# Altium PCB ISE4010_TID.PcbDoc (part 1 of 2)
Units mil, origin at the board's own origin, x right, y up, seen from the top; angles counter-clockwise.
Board outline 9000 x 8000 mil, 4 copper layers (Layer 1 - Top Layer, Layer 2 - GND, Layer 3 - PWR, Layer 4 - Bottom Layer), stack 65.6 mil thick; 159 components, 101 nets, 426 pads, 332 vias.
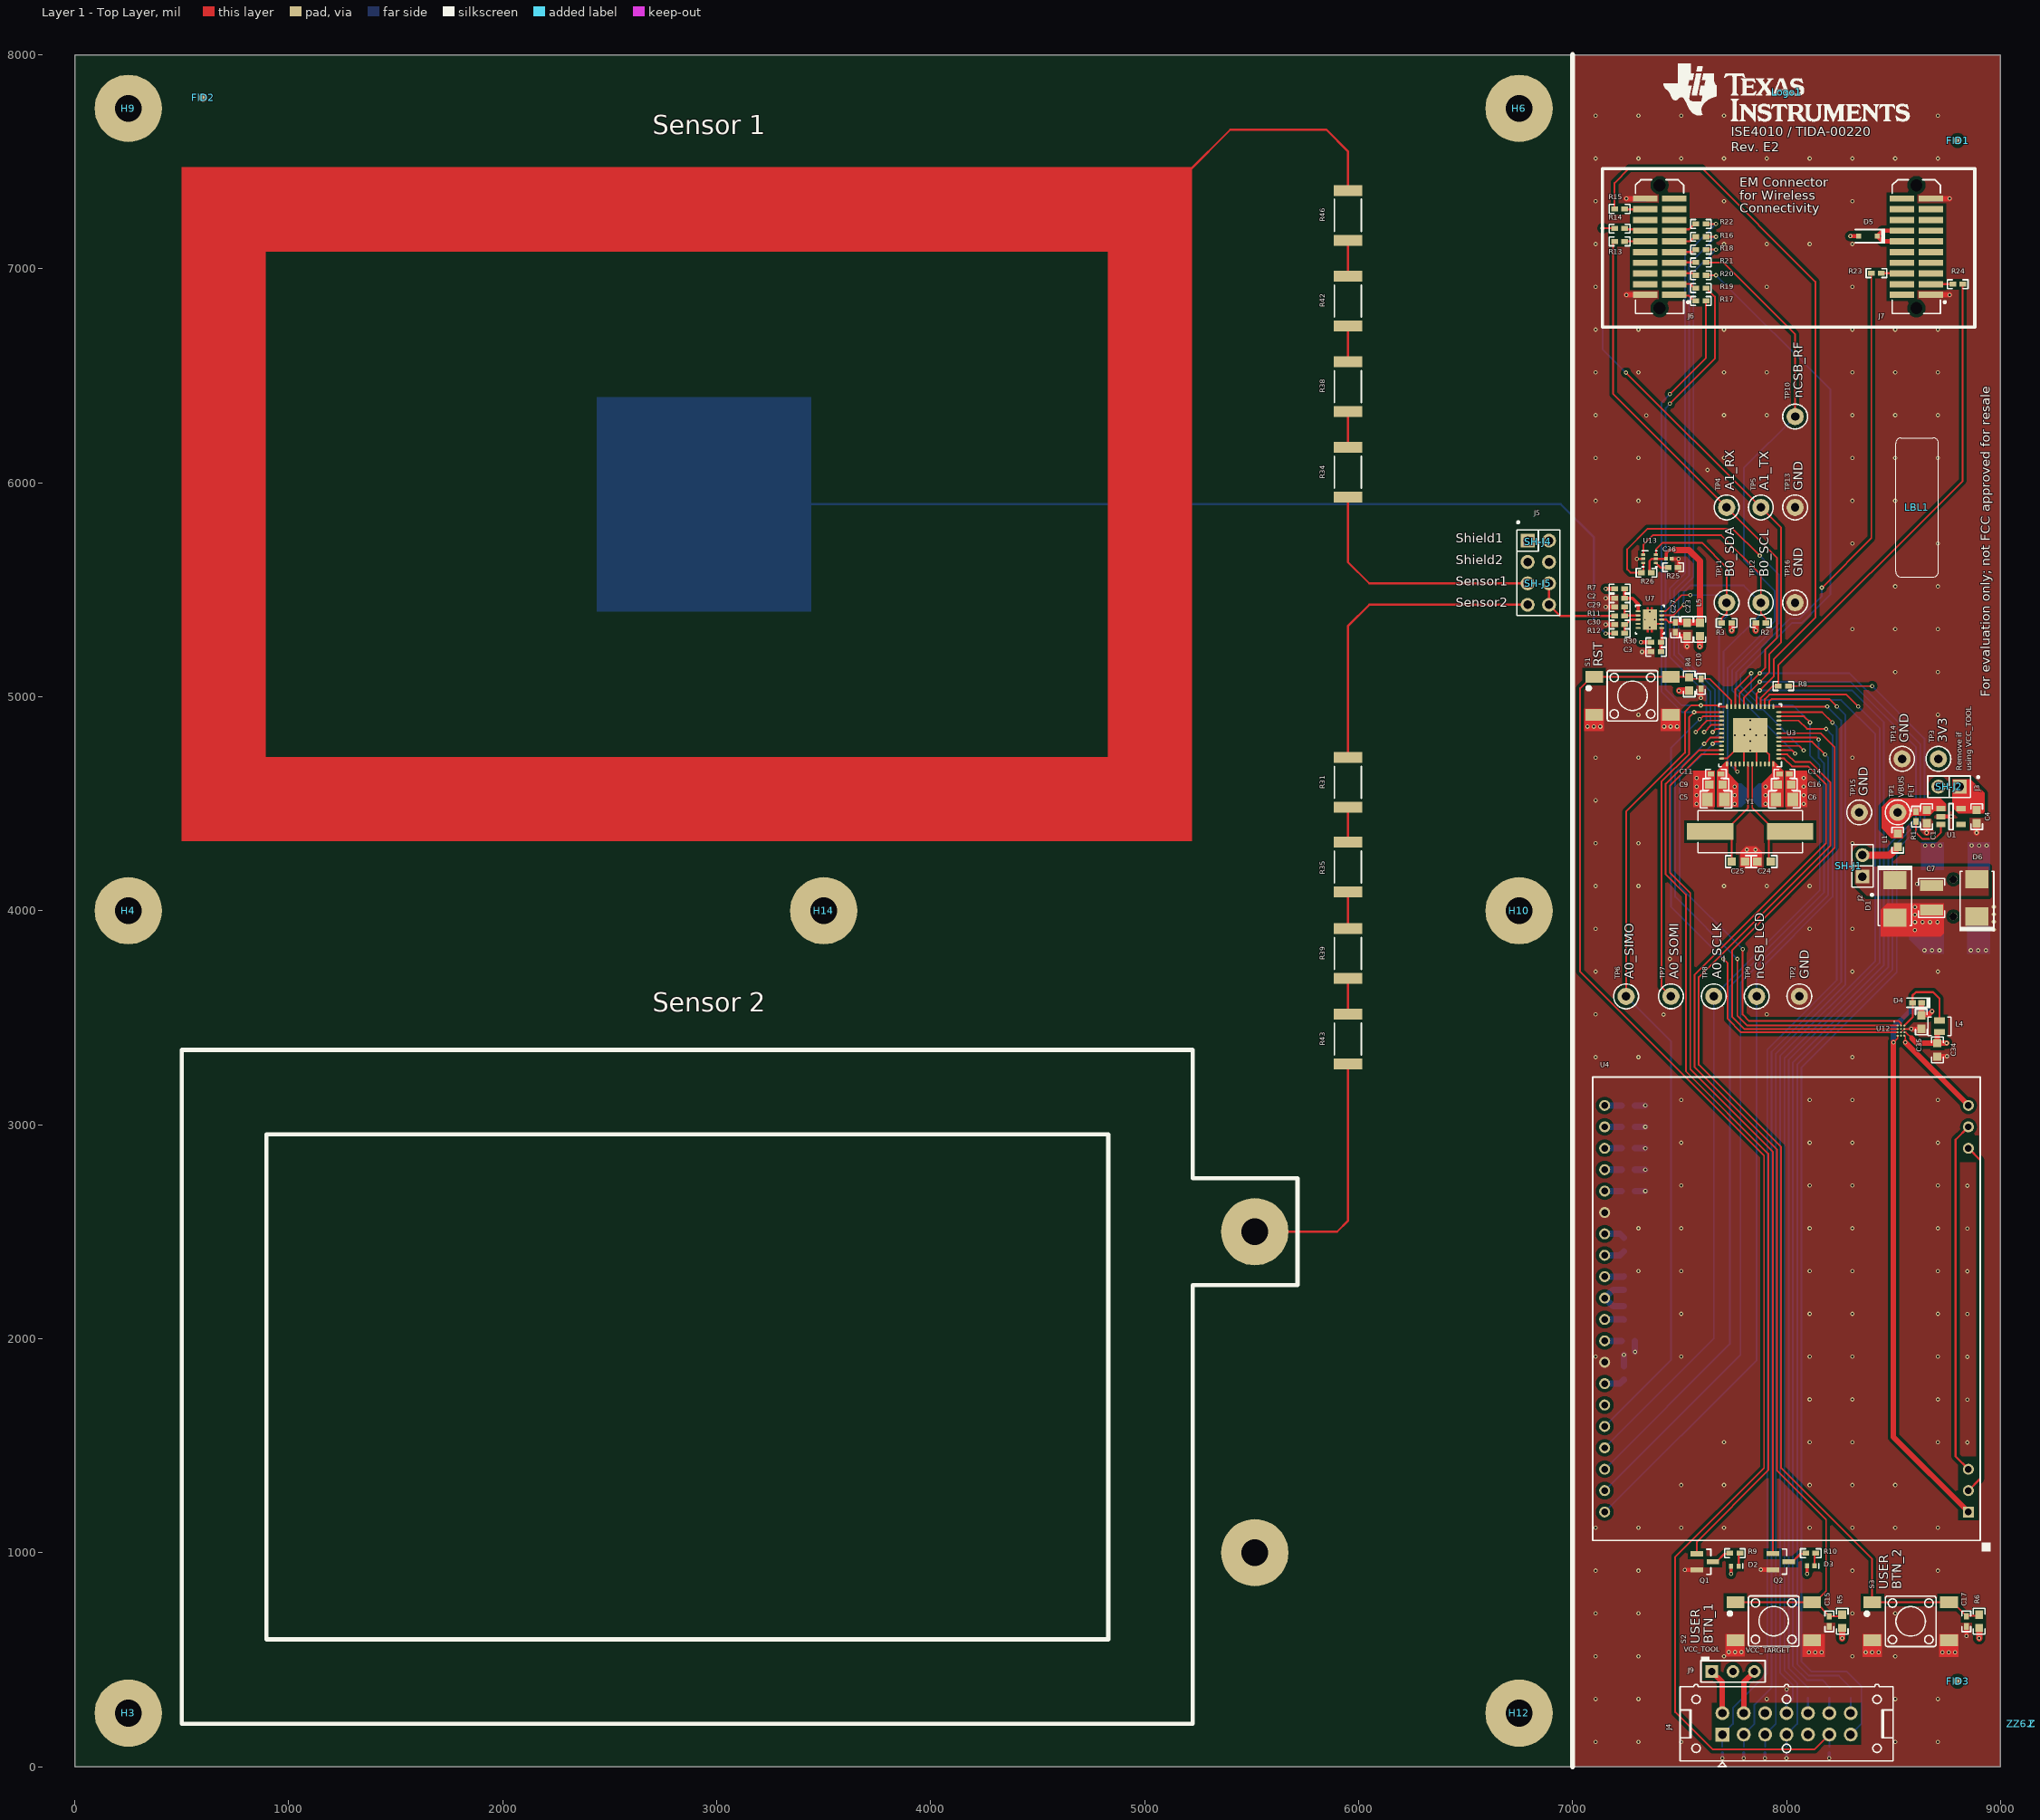
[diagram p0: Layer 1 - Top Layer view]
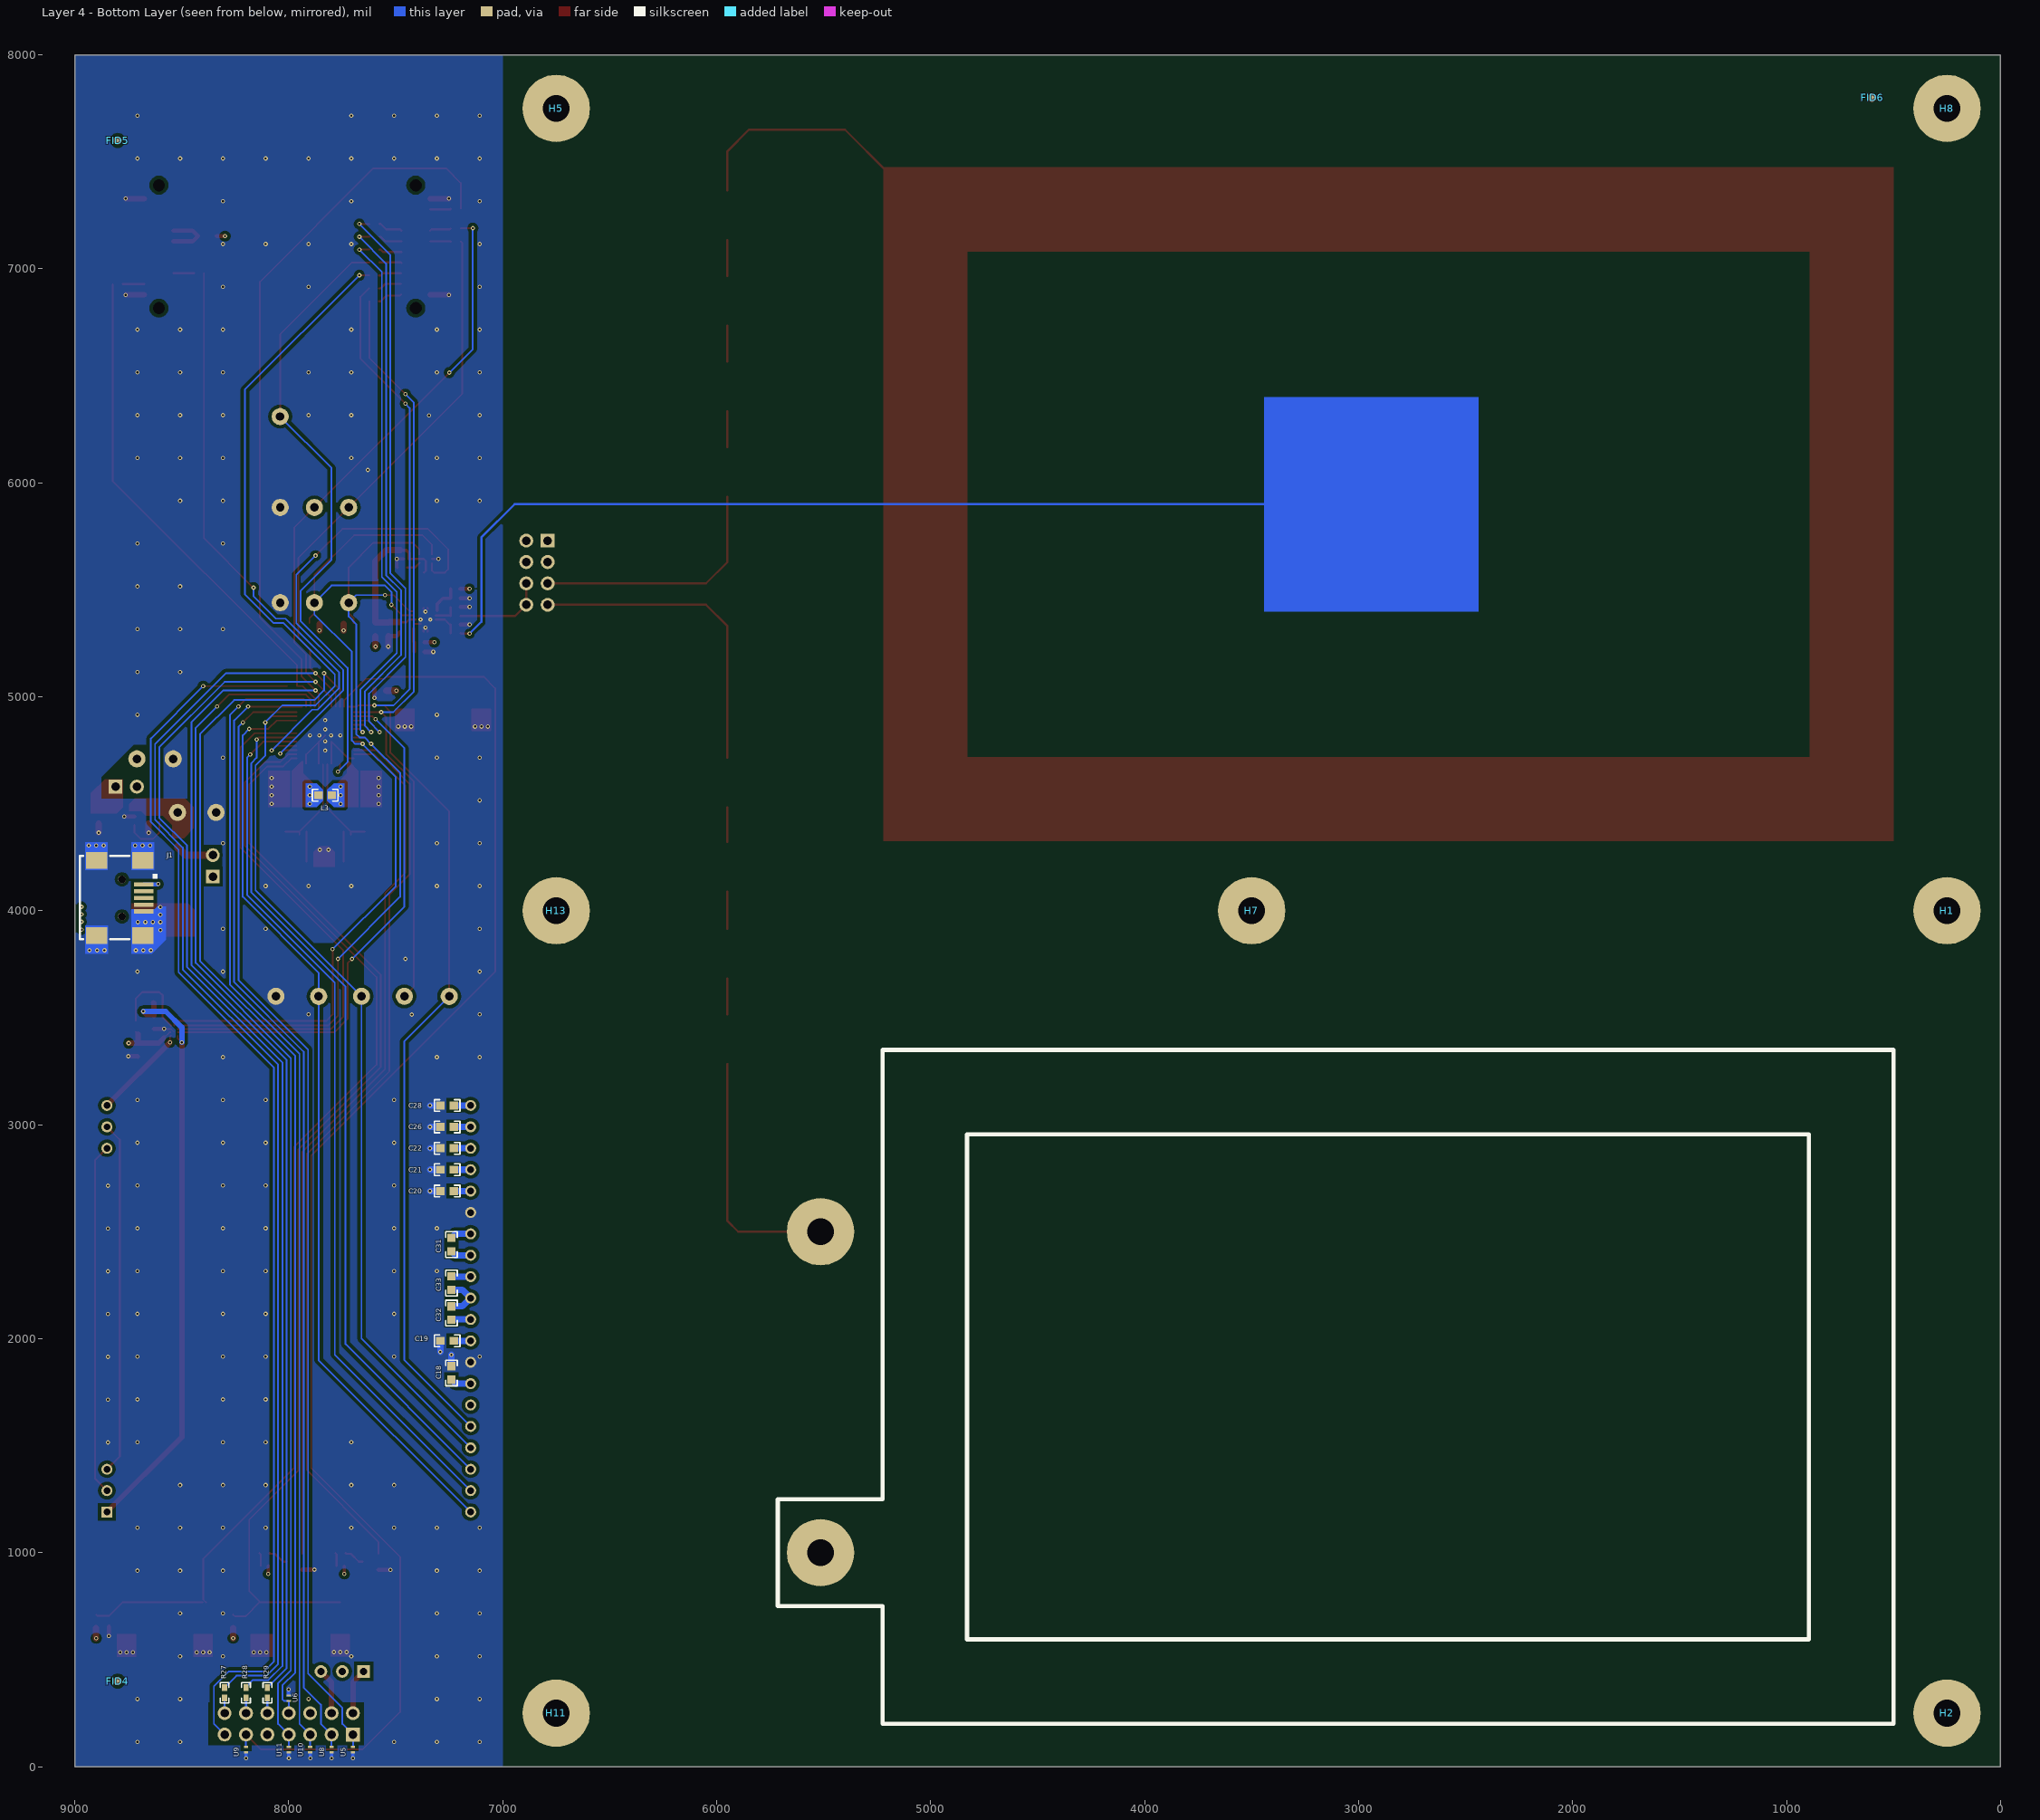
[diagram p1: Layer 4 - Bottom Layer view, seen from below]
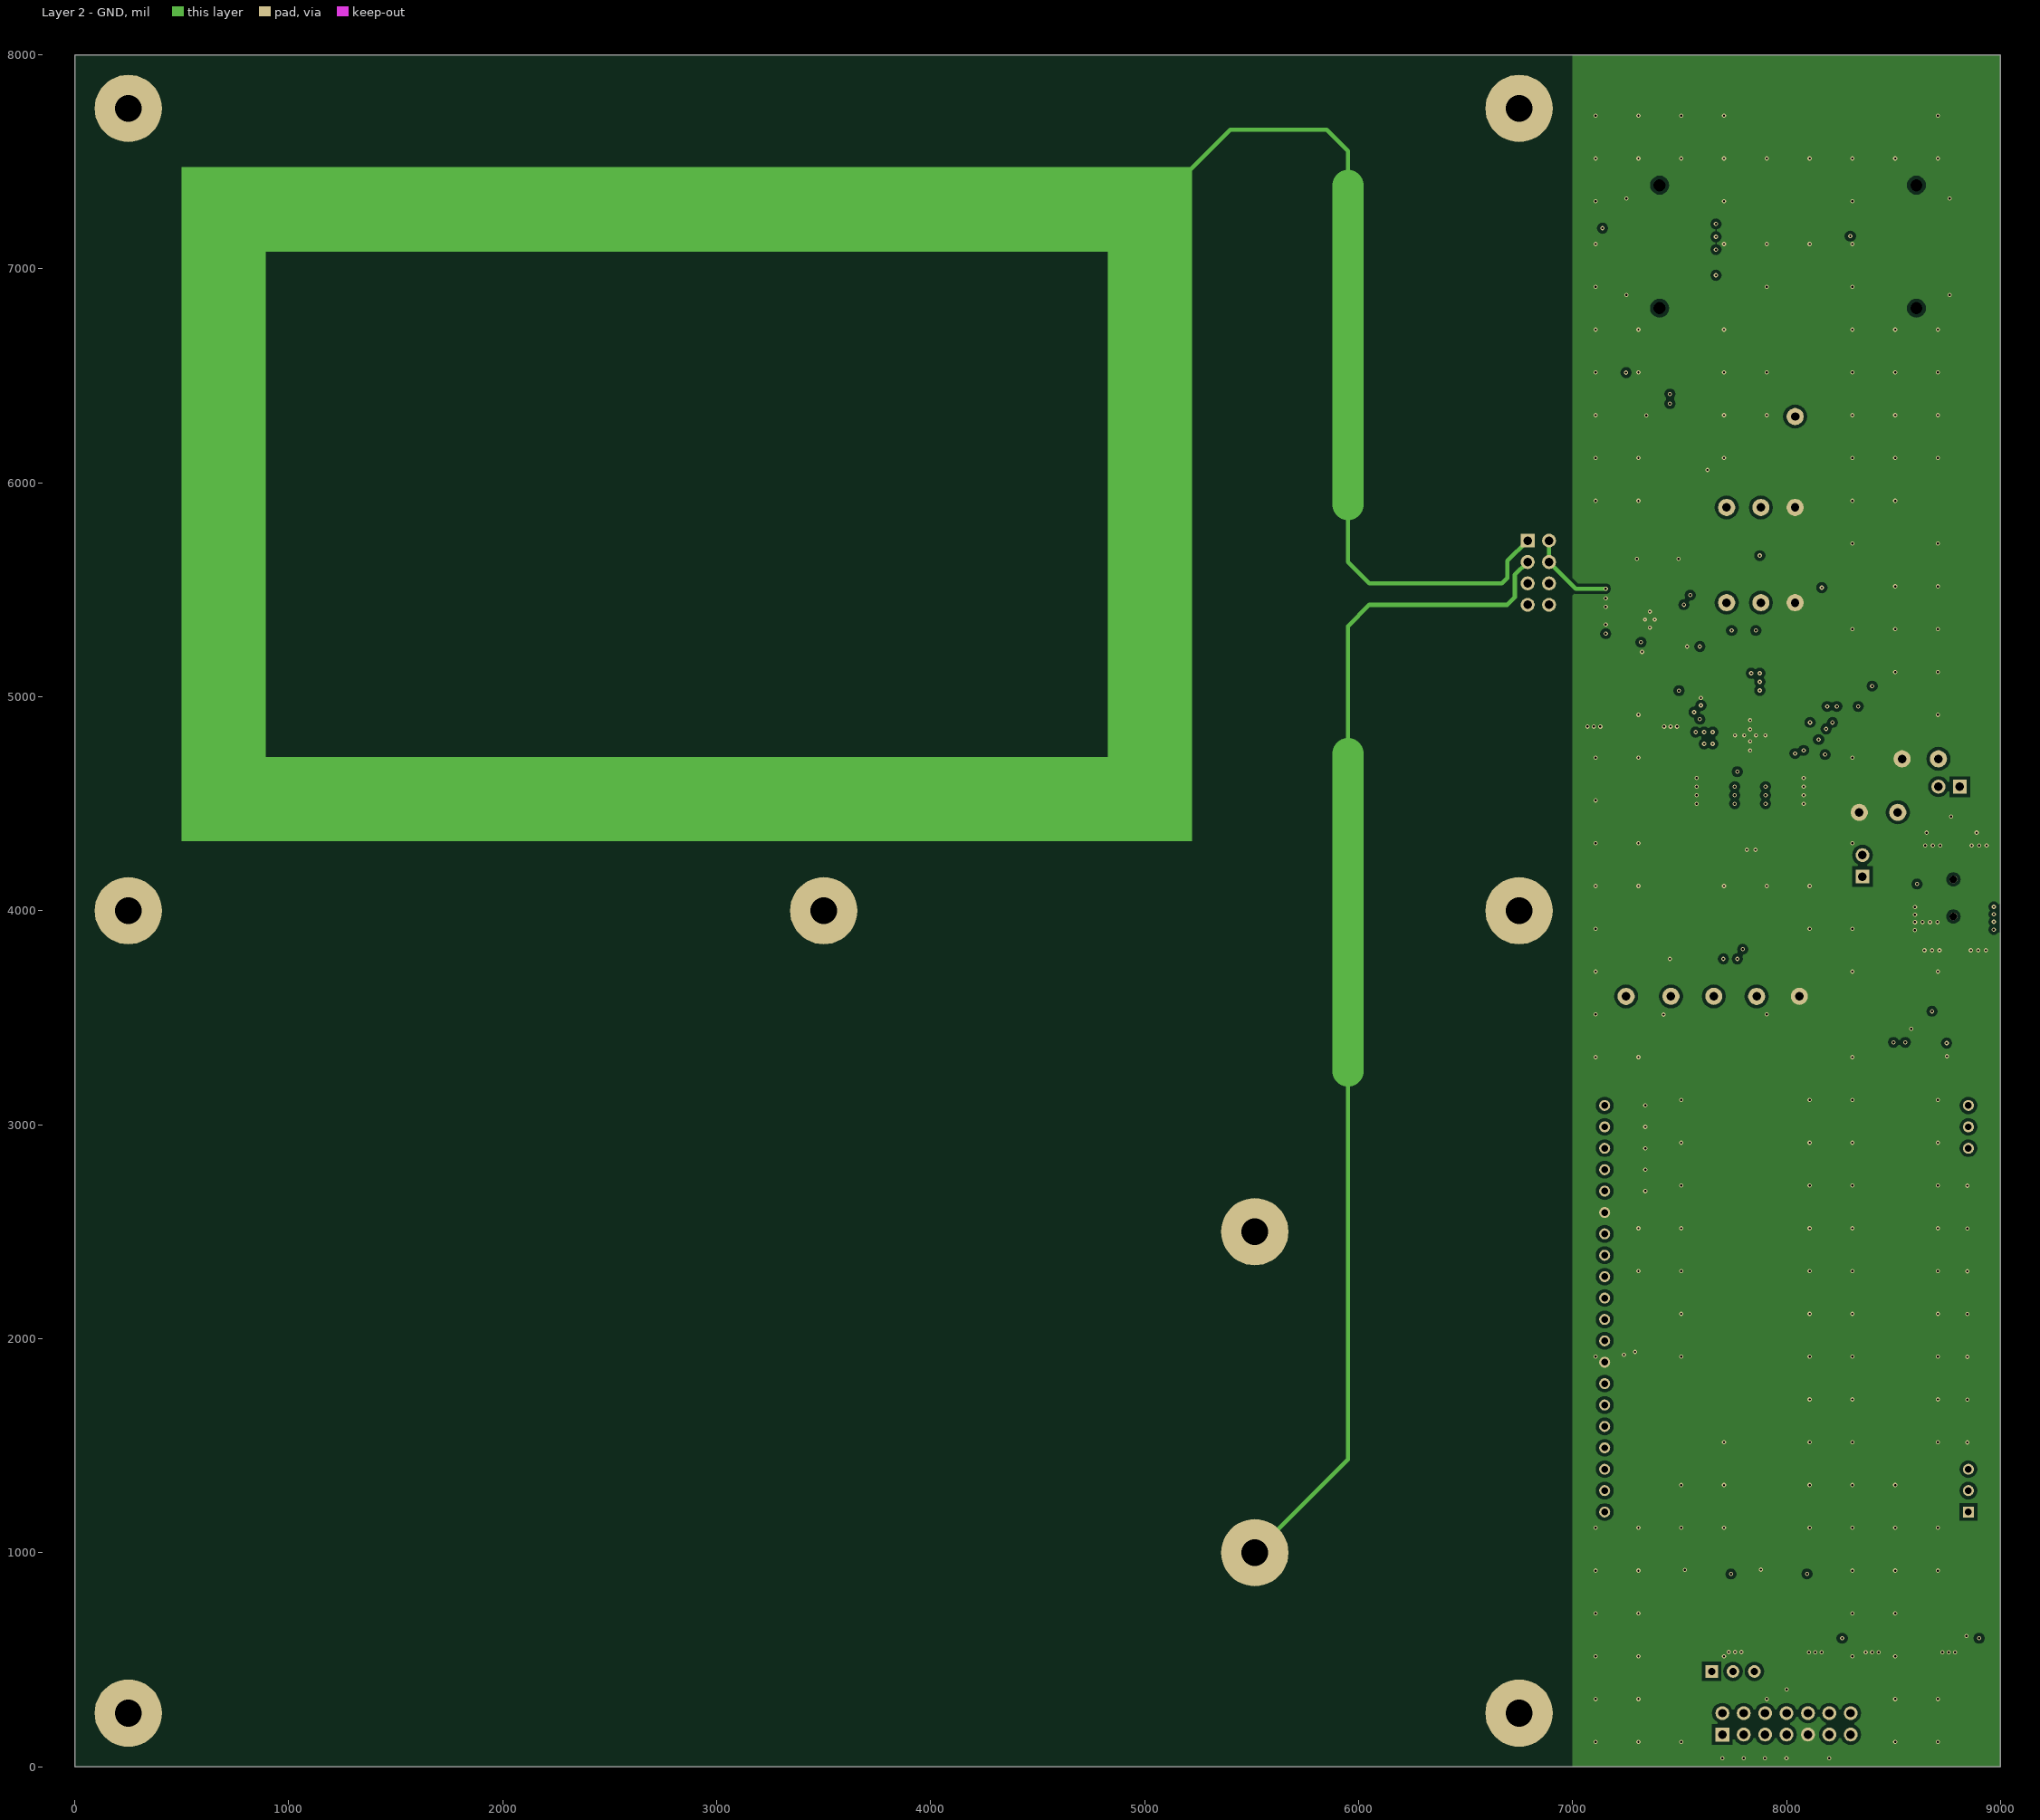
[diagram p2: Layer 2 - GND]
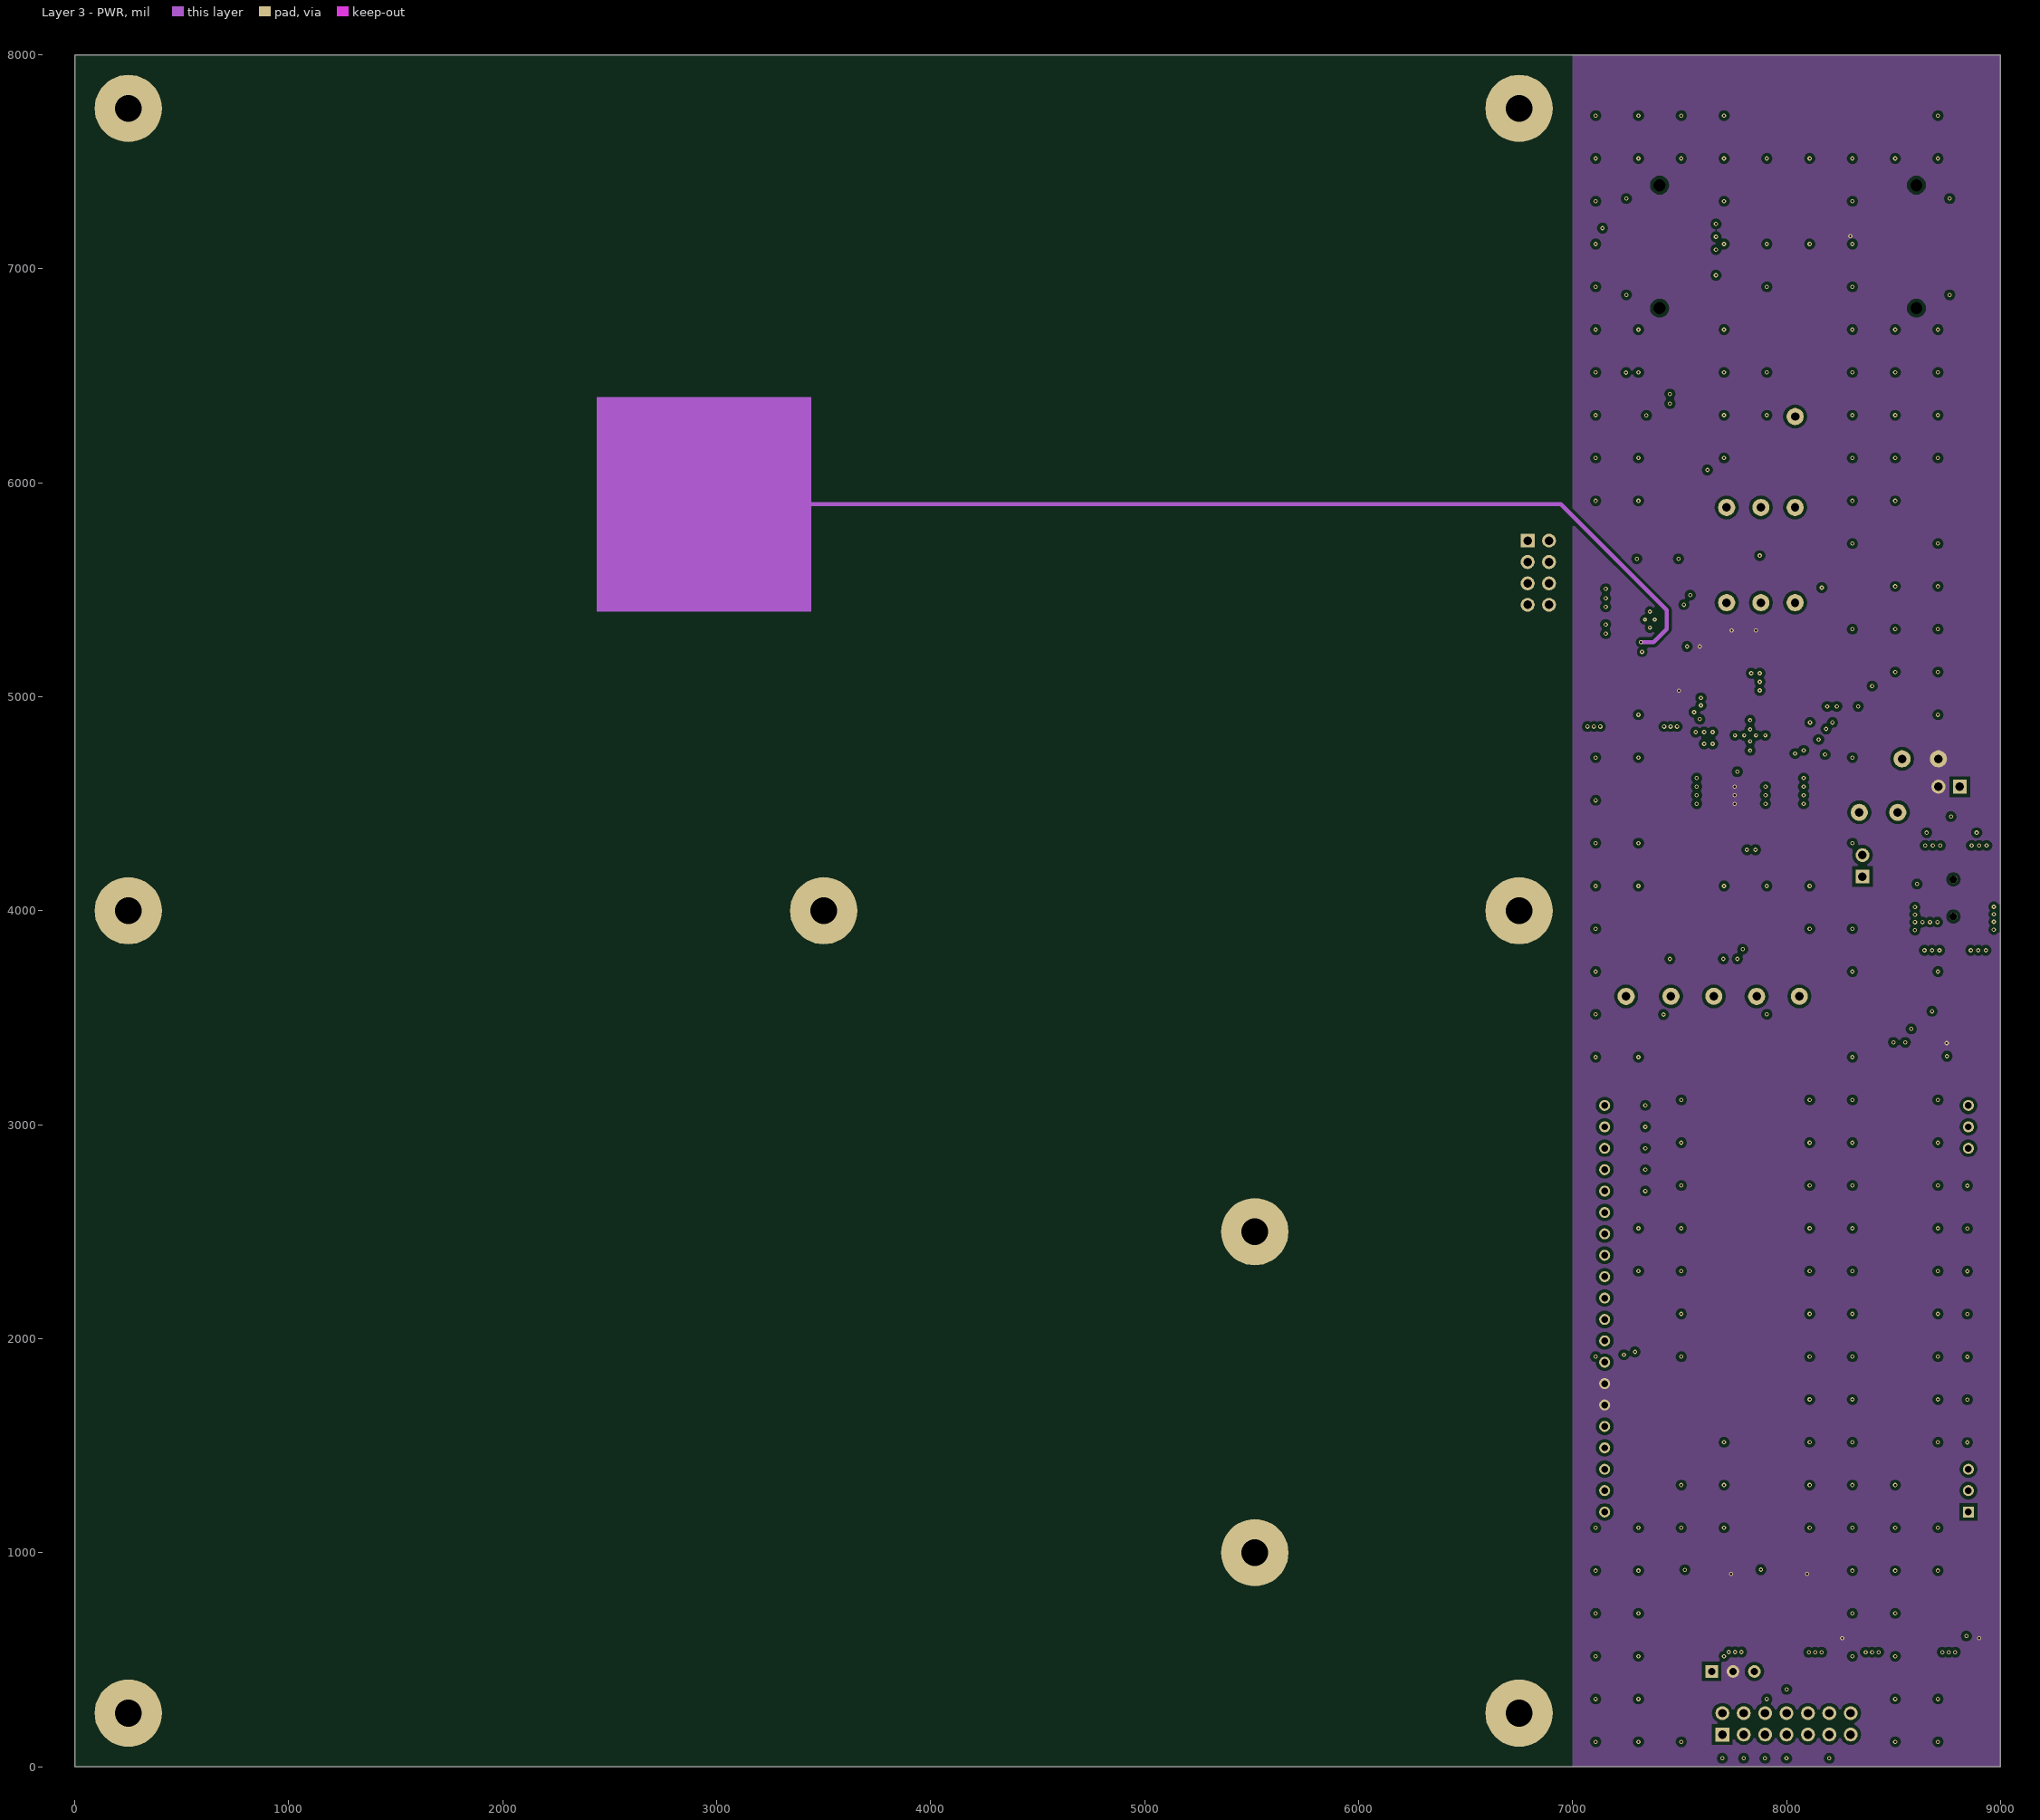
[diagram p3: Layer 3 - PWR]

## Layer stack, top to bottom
Layer 1 - Top Layer: signal copper 1.4
Dielectric: core 10, 370HR, Dk 4.8
Layer 2 - GND: signal copper 1.4
Dielectric: prepreg 40, 370HR, Dk 4.8
Layer 3 - PWR: signal copper 1.4
Dielectric: core 10, 370HR, Dk 4.8
Layer 4 - Bottom Layer: signal copper 1.4

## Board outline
0,0 0,8000 9000,8000 9000,0

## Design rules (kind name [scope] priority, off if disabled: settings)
AcuteAngle [All] p1: minimum=4.50000000000000E+0001 checktracksonly=FALSE
AssemblyTestPointUsage [All] p1: valid=2
Clearance "Stitching GND" [IsStitchingVia and InNet('GND') vs (IsVia and (Not IsStitchingVia)) Or IsPad] p1: gap=8
Clearance Clearance_U12 [InComponent('U12')] p2: gap=3.4
Clearance Clearance_BoardEdge_MountingHoles [OnCopper and InComponentClass('Mounting Holes') vs IsKeepOut] p3: gap=20
Clearance Clearance_BoardEdge_Poly [OnCopper and InPoly vs IsKeepOut] p4: gap=20
Clearance Clearance_BoardEdge [OnCopper and Not InComponentClass('Logo') and not InComponentClass('FiducialMark') and not InRegion(1000,500,4000,800) vs IsKeepOut] p5: gap=20
Clearance Clearance_Poly [InPolygon] p6: gap=15
Clearance [All] p7: gap=5.5
ComponentClearance ComponentClearance_Shunt [InComponentClass('Header') vs InComponentClass('Shunt')] p1 off: gap=0 collisioncheckmode=3 verticalgap=0 showdistances=FALSE
ComponentClearance ComponentClearance_MountingHoles_FiducialMarks [InComponentClass('Mounting Holes') vs InComponentClass('FiducialMark')] p2 off: gap=50 collisioncheckmode=3 verticalgap=10 showdistances=FALSE
ComponentClearance ComponentClearance_Logo [InComponentClass(Logo)] p3 off: gap=50 collisioncheckmode=3 verticalgap=10 showdistances=FALSE
ComponentClearance ComponentClearance_ScrewToNut [(HasFootprint('NY PMS 440 0025 PH')) vs (HasFootprint('Keystone_1902C'))] p4 off: gap=5 collisioncheckmode=3 verticalgap=10 showdistances=FALSE
ComponentClearance ComponentClearance_MountingHoles [InComponentClass('Mounting Holes')] p5 off: gap=250 collisioncheckmode=3 verticalgap=100000 showdistances=FALSE
ComponentClearance ComponentClearance_SmallPassives [HasFootprint('0201*') or HasFootprint('0402*') or HasFootprint('0508') or HasFootprint('0603*') or HasFootprint('0612') or HasFootprint('0805*') or HasFootprint('0815*') or HasFootprint('0830*') or HasFootprint('1206*') or HasFootprint('1210*') or HasFootprint('1808*') or HasFootprint('1812*') or HasFootprint('1825*') or HasFootprint('2010*') or HasFootprint('2220*') or HasFootprint('2225*') or HasFootprint('2512*') or HasFootprint('2728*') or HasFootprint('3518*') vs HasFootprint('0201*') or HasFootprint('0402*') or HasFootprint('0508') or HasFootprint('0603*') or HasFootprint('0612') or HasFootprint('0805*') or HasFootprint('0815*') or HasFootprint('0830*') or HasFootprint('1206*') or HasFootprint('1210*') or HasFootprint('1808*') or HasFootprint('1812*') or HasFootprint('1825*') or HasFootprint('2010*') or HasFootprint('2220*') or HasFootprint('2225*') or HasFootprint('2512*') or HasFootprint('2728*') or HasFootprint('3518*')] p6 off: gap=20 collisioncheckmode=3 verticalgap=10 showdistances=FALSE
ComponentClearance ComponentClearance_THtoSMT [IsThruComponent vs IsSMTComponent] p7 off: gap=100 collisioncheckmode=3 verticalgap=100000 showdistances=FALSE
ComponentClearance ComponentClearance_THtoTH [IsThruComponent vs IsThruComponent] p8 off: gap=118.11 collisioncheckmode=3 verticalgap=100000 showdistances=FALSE
ComponentClearance [All] p9 off: gap=5 collisioncheckmode=3 verticalgap=10 showdistances=FALSE
DiffPairsRouting [All] p1: maxlimit=100 minlimit=10 mostfreqgap=10 maxuncoupledlength=1000
FabricationTestPointUsage TestPointUsage [All] p1: valid=2 allowmultiple=FALSE
FabricationTestpoint Testpoint [All] p1: side=3 testpointundercomponent=TRUE minsize=40 maxsize=100 preferedsize=60 minholesize=0 maxholesize=40 preferedholesize=32 testpointgrid=1 allowsidetop=TRUE allowsidebottom=TRUE usegrid=TRUE gridtolerance=0.01
FanoutControl Fanout_LCC [IsLCC] p1: bgadir=Out bgaviamode=Centered fanoutstyle=Auto fanoutdirection=Alternating viagrid=1 // Fanout_LCC (Default Rule)
FanoutControl Fanout_BGA [IsBGA] p2: bgadir=Out bgaviamode=Centered fanoutstyle=Auto fanoutdirection=Alternating viagrid=1 // Fanout_BGA (Default Rule)
FanoutControl Fanout_Default [All] p4: bgadir=Out bgaviamode=Centered fanoutstyle=Auto fanoutdirection=Alternating viagrid=1 // Fanout_Default (Default Rule)
FanoutControl Fanout_Small [(CompPinCount < 5)] p5: bgadir=Out bgaviamode=Centered fanoutstyle=Auto fanoutdirection=OutThenIn viagrid=1 // Fanout_Small (Default Rule)
HoleSize [All] p1: absolutevalues=TRUE maxlimit=550 minlimit=5 maxpercent=80.000 minpercent=20.000
MinimumAnnularRing MinimumAnnularRing_ThermalPadVias [IsVia and InAnyComponent] p1: minimumring=5.91
MinimumAnnularRing [All] p2: minimumring=5
MinimumSolderMaskSliver MinimumSolderMaskSliver_Logo [InComponentClass('Logo') vs InComponentClass('Logo')] p1: minsoldermaskwidth=0.7
MinimumSolderMaskSliver [All] p2: minsoldermaskwidth=4
NetAntennae [All] p1 off: netantennaetolerance=0
PlaneClearance [All] p1: clearance=10
PlaneConnect [All] p1: planeconnectstyle=Relief reliefexpansion=10 reliefentries=4 reliefconductorwidth=10 reliefairgap=10
PolygonConnect [All] p1: connectstyle=Direct reliefconductorwidth=10 reliefentries=4 polygonreliefangle="90 Angle" airgapwidth=10
RoutingVias ThermalPadVias [IsVia and InAnyComponent] p1: holewidth=7.87 width=19.68 viastyle="Through Hole" minholewidth=7.87 minwidth=19.68 maxholewidth=12.99 maxwidth=23.62
RoutingVias [All] p2: holewidth=12 width=28 viastyle="Through Hole" minholewidth=5 minwidth=20 maxholewidth=100 maxwidth=150
SMDToCorner [All] p1: distance=30000
SilkToSilkClearance [All] p1: silktosilkclearance=5
SilkscreenOverComponentPads [IsPad] p1: minsilkscreentomaskgap=4
SolderMaskExpansion [All] p1: expansion=3
Width "Schematic Width Constraint_4" [InNet('VBUS_FLT')] p1: maxlimit=100 minlimit=5 preferedwidth=25
Width "Schematic Width Constraint_3" [InNet('NetC7_1')] p2: maxlimit=100 minlimit=5 preferedwidth=25
Width "Schematic Width Constraint_2" [InNet('NetC4_2')] p3: maxlimit=100 minlimit=5 preferedwidth=25
Width "Schematic Width Constraint" [InNet('3V3')] p4: maxlimit=100 minlimit=5 preferedwidth=25
Width [All] p5: maxlimit=394 minlimit=4 preferedwidth=10 checkconnectedcopper=TRUE
12 further rules are at their usual default settings.

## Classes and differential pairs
component class Header: J3 J5
component class AssemblyNote: ZZ1 ZZ2 ZZ3 ZZ4 ZZ5 ZZ6 ZZ6.A ZZ6.B ZZ6.C ZZ6.D
component class FiducialMark: FID1 FID2 FID3 FID4 FID5 FID6
component class ISE4010_TID_Hardware: FID1 FID2 FID3 FID4 FID5 FID6 H1 H2 H3 H4 H5 H6 H7 H8 H9 H10 H11 H12 H13 H14 LBL1 Logo1 ZZ1 ZZ2 ZZ3 ZZ4 ZZ5 ZZ6 ZZ6.A ZZ6.B ZZ6.C ZZ6.D
component class Logo: Logo1
component class ISE4010_MSP430: C1 C4 C5 C6 C7 C9 C10 C11 C14 C15 C16 C17 C24 C25 D1 D2 D3 D5 D6 J1 J2 J3 J4 J6 J7 J9 L1 L3 Q1 Q2 R1 R2 R3 R4 R5 R6 R8 R9 R10 R13 R14 R15 R16 R17 R18 R19 R20 R21 R22 R23 R24 R27 R28 R29 S1 S2 S3 SH-J1 SH-J2 TP1 TP2 TP3 TP4 TP5 TP6 TP7 TP8 TP9 TP10 TP11 TP12 TP13 TP14 TP15 TP16 U1 U3 U5 U6 U8 U9 U10 U11 Y1
component class ISE4010_FDC_LCD: C2 C3 C18 C19 C20 C21 C22 C23 C26 C27 C28 C29 C30 C31 C32 C33 C34 C35 C36 D4 J5 L4 L5 R7 R11 R12 R25 R26 R30 R31 R34 R35 R38 R39 R42 R43 R46 SH-J4 SH-J5 U4 U7 U12 U13
component class Shunt: SH-J1 SH-J2 SH-J4 SH-J5
component class "Mounting Holes": H3 H4 H6 H9 H10 H12 H14
component class Label: LBL1

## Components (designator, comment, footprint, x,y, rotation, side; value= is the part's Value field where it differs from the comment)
C1 "GRM188R71A225KE15D" 0603 8655,4440 r90 top
C2 "Used in BOM report" 0402 7220,5460 r180 top
C3 "Used in BOM report" 0402 7390,5210 r180 top
C4 "GRM188R71A225KE15D" 0603 8888.54,4440 r90 top
C5 "C2012X7R0J106M125AB" 0805_HV 7670,4520 r180 top
C6 "C2012X7R0J106M125AB" 0805_HV 7990,4520 r0 top
C7 "C1210C102KGRACTU" 1210 8677.64,4060 r270 top
C9 "C1608X7R1C105K" 0603 7670,4590 r0 top
C10 "C1005X7R1H222K" 0402 7600,5060 r270 top
C11 "GRM155R71C104KA88D" 0402 7670,4640 r0 top
C14 "GRM155R71C104KA88D" 0402 7990,4640 r180 top
C15 "C1005X7R1H222K" 0402 8200.25,679.12 r270 top
C16 "C1608X7R1C105K" 0603 7990,4590 r180 top
C17 "C1005X7R1H222K" 0402 8840.25,679.12 r270 top
C18 "C1608X7R1C105K" 0603 7240,1840 r90 bottom
C19 "C1608X7R1C105K" 0603 7260,1990 r0 bottom
C20 "C1608X7R1C105K" 0603 7260,2690 r0 bottom
C21 "C1608X7R1C105K" 0603 7260,2790 r0 bottom
C22 "C1608X7R1C105K" 0603 7260,2890 r0 bottom
C23 "C1608X7R1C105K" 0603 7535,5315 r270 top
C24 "GRM1885C2A180JA01D" 0603 7895,4230 r180 top
C25 "GRM1885C2A180JA01D" 0603 7775,4230 r0 top
C26 "C1608X7R1C105K" 0603 7260,2990 r0 bottom
C27 "GRM155R71C104KA88D" 0402 7480,5325 r90 top
C28 "C1608X7R1C105K" 0603 7260,3090 r0 bottom
C29 "GRM1555C1H820JA01D" 0402 7220,5420 r0 top
C30 "GRM1555C1H820JA01D" 0402 7220,5337.99 r0 top
C31 "C1608X7R1C105K" 0603 7240,2440 r90 bottom
C32 "C1608X7R1C105K" 0603 7240,2120 r90 bottom
C33 "C1608X7R1C105K" 0603 7240,2260 r90 bottom
C34 "GRM188R71A225KE15D" 0603 8704.92,3349.92 r270 top
C35 "UMK107AB7105KA-T" 0603 8629.92,3479.92 r270 top
C36 "GRM033R71A103KA01D" 0201 7450,5645 r0 top
D1 "1SMB5919BT3G" SMB 8506.54,4055.39 r270 top
D2 "SML-P12PTT86" SML-P1_GREEN 7758.43,937.4 r180 top
D3 "SML-P12PTT86" SML-P1_GREEN 8113.43,937.86 r180 top
D4 "NSR0240V2T1G" SOD-523 8609.92,3569.92 r180 top
D5 "1SS315TPH3F" sod-323 8381,7153 r180 top
D6 "SMBJ6.0CA" SMB 8890,4060 r90 top
FID1 "Fiducial" Fiducial10-20 8800,7600 r0 top
FID2 "Fiducial" Fiducial10-20 600,7800 r0 top
FID3 "Fiducial" Fiducial10-20 8800,400 r0 top
FID4 "Fiducial" Fiducial10-20 8800,400 r180 bottom
FID5 "Fiducial" Fiducial10-20 8800,7600 r180 bottom
FID6 "Fiducial" Fiducial10-20 600,7800 r180 bottom
H1 "1902C" Keystone_1902C#1 250,4000 r180 bottom
H2 "1902C" Keystone_1902C#2 250.53,250 r180 bottom
H3 "NY PMS 440 0025 PH" "NY PMS 440 0025 PH" 250,250 r0 top locked
H4 "NY PMS 440 0025 PH" "NY PMS 440 0025 PH" 250,4000 r0 top
H5 "1902C" Keystone_1902C#2 6750.53,7750 r180 bottom
H6 "NY PMS 440 0025 PH" "NY PMS 440 0025 PH" 6750,7750 r0 top locked
H7 "1902C" Keystone_1902C#1 3500,4000 r180 bottom
H8 "1902C" Keystone_1902C#2 250.53,7750 r180 bottom
H9 "NY PMS 440 0025 PH" "NY PMS 440 0025 PH" 250,7750 r0 top locked
H10 "NY PMS 440 0025 PH" "NY PMS 440 0025 PH" 6750,4000 r0 top
H11 "1902C" Keystone_1902C#2 6750.3,250.01 r180 bottom
H12 "NY PMS 440 0025 PH" "NY PMS 440 0025 PH" 6750,250 r0 top locked
H13 "1902C" Keystone_1902C#1 6750,4000 r180 bottom
H14 "NY PMS 440 0025 PH" "NY PMS 440 0025 PH" 3500,4000 r0 top
J1 "1734035-2" CONN_USB-Mini-B-1734035-2 8780,4060 r270 bottom
J2 "90120-0122" CONN_90120-0122 8355,4210 r90 top
J3 "90120-0122" CONN_90120-0122 8760,4580 r180 top
J4 "SBH11-PBPC-D07-ST-BK" CONN_SBH11-PBPC-D07-ST-BK 8000,200 r0 top locked
J5 "TSW-104-07-G-D" TSW-104-07-G-D 6840,5580 r270 top
J6 "TFM-110-02-L-D-A" Samtec_TFM-110-02-L-D-A 7406.99,7103.51 r90 top
J7 "TFM-110-02-L-D-A" Samtec_TFM-110-02-L-D-A 8606.99,7103.51 r90 top
J9 "800-10-003-10-001000" Mill-Max_800-10-003-10-001000 7750,445 r0 top
L1 "BLM18SG331TN1D" 0603 8520,4330 r90 top
L3 "BLM18SG331TN1D" 0603 7830,4540 r0 bottom
L4 "VLF252015MT-100M" IND_VLF252015 8714.93,3459.92 r90 top
L5 "BLM18SG331TN1D" 0603 7595,5315 r90 top
LBL1 "Size: 0.65\" x 0.20 \"" Label_650x200 8610,5885 r90 top
Logo1 "Texas Instruments" TI_Stacked_Overlay_Medium 8000,7825 r0 top
Q1 "BSS138" SOT-23 7618.43,957.4 r0 top
Q2 "BSS138" SOT-23 7973.43,957.86 r0 top
R1 "CRCW04020000Z0ED" 0402 8605,4440 r90 top
R2 "CRCW04024K99FKED" 0402 7880,5345 r180 top
R3 "CRCW04024K99FKED" 0402 7720,5345 r0 top
R4 "CRCW060347K5FKEA" 0603 7545,5060 r270 top
R5 "CRCW060347K5FKEA" 0603 8260.25,679.12 r270 top
R6 "CRCW060347K5FKEA" 0603 8900.25,679.12 r270 top
R7 "CRCW04020000Z0ED" 0402 7220,5505 r180 top
R8 "CRCW04020000Z0ED" 0402 7985,5050 r0 top
R9 "CRCW0402221RFKED" 0402 7758.43,997.4 r0 top
R10 "CRCW0402221RFKED" 0402 8113.43,997.86 r0 top
R11 "CRCW040238K3FKED" 0402 7220,5377.99 r0 top
R12 "CRCW040238K3FKED" 0402 7220,5297.99 r0 top
R13 "CRCW04020000Z0ED" 0402 7220,7128.21 r0 top
R14 "CRCW04020000Z0ED" 0402 7220,7188.21 r0 top
R15 "CRCW04020000Z0ED" 0402 7220,7280 r180 top
R16 "CRCW04020000Z0ED" 0402 7600,7150 r180 top
R17 "CRCW04020000Z0ED" 0402 7600,6850 r180 top
R18 "CRCW04020000Z0ED" 0402 7600,7090 r180 top
R19 "CRCW04020000Z0ED" 0402 7600,6910 r0 top
R20 "CRCW04020000Z0ED" 0402 7600,6970 r0 top
R21 "CRCW04020000Z0ED" 0402 7600,7030 r0 top
R22 "CRCW04020000Z0ED" 0402 7600,7210 r0 top
R23 "CRCW04020000Z0ED" 0402 8420,6980 r180 top
R24 "CRCW04020000Z0ED" 0402 8800,6928.21 r180 top
R25 "CRCW04020000Z0ED" 0402 7470,5605 r0 top
R26 "CRCW040210K0FKED" 0402 7345,5580 r0 top
R27 "CRCW04020000Z0ED" 0402 8300,345 r270 bottom
R28 "CRCW04020000Z0ED" 0402 8200,345 r270 bottom
R29 "CRCW04020000Z0ED" 0402 8100,345 r270 bottom
R30 "CRCW04020000Z0ED" 0402 7390,5255 r180 top
R31 "CRCW25120000Z0EG" 2512 5950,4600 r270 top
R34 "CRCW25120000Z0EG" 2512 5950,6050 r90 top
R35 "CRCW25120000Z0EG" 2512 5950,4205 r270 top
R38 "CRCW25120000Z0EG" 2512 5950,6450 r90 top
R39 "CRCW25120000Z0EG" 2512 5950,3800 r270 top
R42 "CRCW25120000Z0EG" 2512 5950,6850 r90 top
R43 "CRCW25120000Z0EG" 2512 5950,3400 r270 top
R46 "CRCW25120000Z0EG" 2512 5950,7250 r90 top
S1 "4-1437565-1" SW_FSM4JSMA 7280,5005 r90 top
S2 "4-1437565-1" SW_FSM4JSMA 7940,680 r90 top
S3 "4-1437565-1" SW_FSM4JSMA 8580.25,679.12 r90 top
SH-J1 "2SN-BK-G" 2SN-BK-G 8290,4210 r90 top
SH-J2 "2SN-BK-G" 2SN-BK-G 8760,4580 r180 top
SH-J4 "2SN-BK-G" 2SN-BK-G 6840,5725 r180 top
SH-J5 "2SN-BK-G" 2SN-BK-G 6840,5530 r180 top
TP1 "5000" Keystone5000 8520,4460 r90 top
TP2 "5001" Keystone5001 8060,3600 r0 top
TP3 "5000" Keystone5000 8710,4710 r90 top
TP4 "5004" Keystone5004 7720,5885 r0 top
TP5 "5004" Keystone5004 7880,5885 r0 top
TP6 "5003" Keystone5003 7250.18,3599.88 r0 top
TP7 "5003" Keystone5003 7460,3600 r0 top
TP8 "5003" Keystone5003 7660,3600 r0 top
TP9 "5003" Keystone5003 7860.18,3599.88 r0 top
TP10 "5003" Keystone5003 8040.18,6309.89 r0 top
TP11 "5004" Keystone5004 7720,5440 r180 top
TP12 "5004" Keystone5004 7880,5440 r0 top
TP13 "5001" Keystone5001 8040,5885 r0 top
TP14 "5001" Keystone5001 8540,4710 r0 top
TP15 "5001" Keystone5001 8340,4460 r0 top
TP16 "5001" Keystone5001 8040,5440 r0 top
U1 "LP5907MFX-3.3/NOPB" DBV0005A_N 8768.54,4440 r0 top
U3 "MSP430FR5969IRGZ" RGZ0048B 7830,4820 r180 top
U4 "EA DOGM128W-6" "LCD-MODULE_EA DOGM128W-6" 8000,2140 r90 top locked
U5 "TPD1E10B06DPYR" DPY0002A 7700,80 r270 bottom
U6 "TPD1E10B06DPYR" DPY0002A 8000,320 r90 bottom
U7 "FDC1004DSC" DSC0010B 7361.13,5360.73 r0 top
U8 "TPD1E10B06DPYR" DPY0002A 7800,80 r270 bottom
U9 "TPD1E10B06DPYR" DPY0002A 8200,80 r270 bottom
U10 "TPD1E10B06DPYR" DPY0002A 7900,80 r270 bottom
U11 "TPD1E10B06DPYR" DPY0002A 8000,80 r270 bottom
U12 "LM3630ATME" YFQ0012AKAR 8534.92,3439.92 r0 top
U13 "TMP112AIDRL" DRL0006A 7360,5645 r0 top
Y1 "ABLS-8.000MHZ-B4-T" XTAL_CSM-7X 7830,4370 r0 top
ZZ1 "This Assembly Note is for PCB labels only" AssemblyNoteLabel 10000,200 r90 top
ZZ2 "These assemblies are ESD sensitive, ESD precautions shall be observed." AssemblyNote 9900,200 r90 top
ZZ3 "These assemblies must be clean and free from flux and all contaminants. Use of no clean flux is not acceptable." AssemblyNote 9800,200 r90 top
ZZ4 "These assemblies must comply with workmanship standards IPC-A-610 Class 2, unless otherwise specified." AssemblyNote 9700,200 r90 top
ZZ5 "Place SH-J1 on J2, SH-J2 on J3, SH-J3 on J9 (pins 2-3), SH-J4 on J5 (pins 1-2), and SH-J5 on J5 (pins 5-6)" AssemblyNote 9600,200 r90 top
ZZ6 "Component BL1 must be assembled to U4 Before U4 is attached to the board." AssemblyNote 9500,200 r90 top
ZZ6.A "Remove protective coverings from BL1 and U4" AssemblyNote 9400,200 r90 top
ZZ6.B "Slide pins of U4 into holes of BL1. BL1 must lie flat on the back of U4." AssemblyNote 9300,200 r90 top
ZZ6.C "Solder U4 - BL1 assembly to the board." AssemblyNote 9200,200 r90 top
ZZ6.D "Solder Pins 1, 2, 3, 18, 19, and 20 of U4 to BL1 from the top to insure electrical continuity." AssemblyNote 9100,200 r90 top

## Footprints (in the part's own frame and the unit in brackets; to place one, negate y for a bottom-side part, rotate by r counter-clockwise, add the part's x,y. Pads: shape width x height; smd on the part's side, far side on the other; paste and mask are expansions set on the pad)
2SN-BK-G [mil] "Samtec STEP model"
  round 1 on Mech3: 0(0,0)
  body extent -78,-39 79,39, height 188
0201 [mm] "Data from Kemet datasheet CC101_COM dated 7/28/11"
  rect 0.46x0.42 smd mask+0.025: 1(-0.33,0) 2(0.33,0)
  body extent -0.31,-0.16 0.31,0.16, height 0.26
0402 [mm] "0402 from SM-752 data"
  rect 0.8x0.6 smd: 1(-0.6,0) 2(0.6,0)
  silkscreen extent -1.22,-0.52 1.22,0.52, body extent -0.55,-0.3 0.55,0.3, height 0.6
0603 [mm] "0603 from SM-752 data"
  rect 1x0.95 smd: 1(-0.8,0) 2(0.8,0)
  silkscreen extent -1.52,-0.69 1.52,0.69, body extent -0.87,-0.47 0.87,0.47, height 0.85
0805_HV [mil] "0805 with 30mil clearance between pads"
  rect 50x63 smd: 1(-40,0) 2(40,0)
  silkscreen extent -74,-40 74,40, body extent -43,-29 43,29, height 43
1210 [mm] "1210 from SM-752 data"
  rect 1.3x2.7 smd: 1(-1.45,0) 2(1.45,0)
  silkscreen extent -2.32,-1.57 2.32,1.57, body extent -1.7,-1.35 1.7,1.35, height 1.35
2512 [mm] "Chip Resistor, Body 6.3x3.2mm, IPC Medium Density"
  rect 1.3x3.4 smd: 1(-2.95,0) 2(2.95,0)
  silkscreen extent -1.9,-1.6 1.9,1.6, body extent -3.22,-1.67 3.22,1.67, height 0.71
AssemblyNote [mil] "Assembly Note"
AssemblyNoteLabel [mil] "Assembly Note for PCB Labels"
CONN_90120-0122 [mm] "Molex"
  rect 1.65x1.65 hole 1.016 mask+0: 1(-1.27,0)
  round 1.65 hole 1.016 mask+0: 2(1.27,0)
  silkscreen extent -3.56,-1.27 2.54,1.27, body extent -2.54,-1.27 2.54,1.27, height 9.29
CONN_SBH11-PBPC-D07-ST-BK [mm] "Sullins recommended land pattern"
  rect 1.65x1.65 hole 1.016 mask+0: 1(-7.62,-1.27)
  round 1.65 hole 1.016 mask+0: 2(-7.62,1.27) 3(-5.08,-1.27) 4(-5.08,1.27) 5(-2.54,-1.27) 6(-2.54,1.27) 7(0,-1.27) 8(0,1.27) 9(2.54,-1.27) 10(2.54,1.27) 11(5.08,-1.27) 12(5.08,1.27) 13(7.62,-1.27) 14(7.62,1.27)
  silkscreen extent -12.64,-5.08 12.64,4.7, body extent -12.64,-4.4 12.64,4.7, height 9.12
CONN_USB-Mini-B-1734035-2 [mm] "Tyco Connectivity recommended land pattern"
  rect 0.5x2.3 smd: 1(-1.6,2.6) 2(-0.8,2.6) 3(0,2.6) 4(0.8,2.6) 5(1.6,2.6)
  rect 2x2.5 smd: 6(4.45,2.5) 7(4.45,-3) 8(-4.45,-3) 9(-4.45,2.5)
  round 0.9 hole 0.9 unplated: 10(2.2,0) 11(-2.2,0)
  silkscreen extent -5,-5 4.9,4.19, body extent -4.95,-5.9 4.95,3.3, height 4.1
DBV0005A_N [mm] "SOT23, 5-Leads, Body 2.9x1.6mm, Pitch 0.95mm, Lead Span 2.8mm, IPC Medium Density"
  rect 1.1x0.65 smd: 1(-1.2,0.95) 2(-1.2,0) 3(-1.2,-0.95) 4(1.2,-0.95) 5(1.2,0.95)
  silkscreen extent -0.25,-1.55 0.25,1.55, body extent -1.42,-1.46 1.42,1.46, height 1.08
DPY0002A [mm] "R-PX2SON-N2"
  rect 0.25x0.5 smd: 1(-0.325,0) 2(0.325,0)
  body extent -0.55,-0.35 0.55,0.35, height 0.4
DRL0006A [mm] "SOTFL, 6-Flat Leads, Body 1.2x1.6x0.6mm, Pitch 0.5mm, TI recommended"
  rect 0.5x0.3 smd mask+0.025: 1(-0.75,0.5) 2(-0.75,0) 3(-0.75,-0.5) 4(0.75,-0.5) 5(0.75,0) 6(0.75,0.5)
  silkscreen extent -0.9,-0.95 0.9,0.95, body extent -0.85,-0.85 0.85,0.85, height 0.62
DSC0010B [mm] "SON, 10-Leads, Body 3x3mm, Pitch 0.5mm, Thermal Pad 2.4x1.65mm, TI Recommended"
  oval 0.6x0.24 smd mask+0.025: 1(-1.4,1) 2(-1.4,0.5) 3(-1.4,0) 4(-1.4,-0.5) 5(-1.4,-1) 6(1.4,-1) 7(1.4,-0.5) 8(1.4,0) 9(1.4,0.5) 10(1.4,1)
  rect 1.65x2.4 smd paste-0.825: 11(0,0)
  Layer 1 - Top Layer region: -0.39,-1.5 -0.11,-1.5 -0.11,-1.15 -0.39,-1.15
  Layer 1 - Top Layer region: 0.39,-1.15 0.11,-1.15 0.11,-1.5 0.39,-1.5
  Layer 1 - Top Layer region: 0.39,1.5 0.11,1.5 0.11,1.15 0.39,1.15
  Layer 1 - Top Layer region: -0.39,1.15 -0.11,1.15 -0.11,1.5 -0.39,1.5
  silkscreen extent -1.7,-1.7 1.7,1.7, body extent -1.57,-1.57 1.57,1.57, height 0.81
Fiducial10-20 [mm]
  round 1 smd paste-0.5 mask+0.5: 1(0,0)
IND_VLF252015 [mm] "TDK"
  rect 0.75x1.3 smd: 1(-0.675,0) 2(0.675,0)
  silkscreen extent -1.12,-1.38 1.12,1.38, body extent -1.1,-1.35 1.1,1.35, height 1.5
Keystone5000 [mil] "For Keystone 500x miniature loop terminals"
  round 80 hole 40: 1(0,0)
  silkscreen extent -58,-58 58,58, body extent -49,-49 49,49, height 182
Keystone5001 [mil] "For Keystone 500x miniature loop terminals"
  round 80 hole 40: 1(0,0)
  silkscreen extent -58,-58 58,58, body extent -49,-49 49,49, height 182
Keystone5003 [mil] "For Keystone 500x miniature loop terminals"
  round 80 hole 40: 1(0,0)
  silkscreen extent -58,-58 58,58, body extent -49,-49 49,49, height 182
Keystone5004 [mil] "For Keystone 500x miniature loop terminals"
  round 80 hole 40: 1(0,0)
  silkscreen extent -58,-58 58,58, body extent -49,-49 49,49, height 182
Keystone_1902C#1 [mil] "Hex Standoff, 4-40 threaded, nylon"
  round 1 on Mech4: 0(0,0)
  body extent -145,-126 146,126, height 501
Keystone_1902C#2 [mil] "Hex Standoff, 4-40 threaded, nylon"
  body extent -145,-126 146,126, height 501
Label_650x200 [mil] "Thermal Transfer Label"
  round 1 on Mech13: 0(0,0)
  silkscreen extent -325,-100 325,100, body extent -326,-101 326,101, height 1
"LCD-MODULE_EA DOGM128W-6" [mm] "LCD-MODULE"
  rect 1.3x1.3 hole 0.8: 1(-24.13,-21.59)
  round 1.3 hole 0.8: 2(-21.59,-21.59) 3(-19.05,-21.59) 18(19.05,-21.59) 19(21.59,-21.59) 20(24.13,-21.59) 21(24.13,21.59) 22(21.59,21.59) 23(19.05,21.59) 24(16.51,21.59) 25(13.97,21.59) 26(11.43,21.59) 27(8.89,21.59) 28(6.35,21.59) 29(3.81,21.59) 30(1.27,21.59) 31(-1.27,21.59) 32(-3.81,21.59) 33(-6.35,21.59) 34(-8.89,21.59) 35(-11.43,21.59) 36(-13.97,21.59) 37(-16.51,21.59) 38(-19.05,21.59) 39(-21.59,21.59) 40(-24.13,21.59)
  silkscreen extent -28.8,-24.21 27.5,23, body extent -27.5,-23 27.5,23, height 7.31
Mill-Max_800-10-003-10-001000 [mm] "Mill-Max"
  rect 1.5x1.5 hole 0.85: 1(-2.54,0)
  round 1.5 hole 0.85: 2(0,0) 3(2.54,0)
  silkscreen extent -3.81,-1.27 3.81,1.78, body extent -3.81,-1.27 3.81,1.27, height 8.13
"NY PMS 440 0025 PH" [mm] "4-40 nylon screw and mounting hole"
  round 8 hole 3.2: 1(0,0)
  body extent -3.3,-3.3 3.3,3.3, height 2.69
RGZ0048B [mm] "QFN, 48-Leads, Body 7x7mm, Pitch 0.5mm, Thermal Pad 5.15x5.15mm, TI Recommended"
  oval 0.6x0.24 smd mask+0.025: 1(-3.4,2.75) 2(-3.4,2.25) 3(-3.4,1.75) 4(-3.4,1.25) 5(-3.4,0.75) 6(-3.4,0.25) 7(-3.4,-0.25) 8(-3.4,-0.75) 9(-3.4,-1.25) 10(-3.4,-1.75) 11(-3.4,-2.25) 12(-3.4,-2.75) 25(3.4,-2.75) 26(3.4,-2.25) 27(3.4,-1.75) 28(3.4,-1.25) 29(3.4,-0.75) 30(3.4,-0.25) 31(3.4,0.25) 32(3.4,0.75) 33(3.4,1.25) 34(3.4,1.75) 35(3.4,2.25) 36(3.4,2.75)
  oval 0.24x0.6 smd mask+0.025: 13(-2.75,-3.4) 14(-2.25,-3.4) 15(-1.75,-3.4) 16(-1.25,-3.4) 17(-0.75,-3.4) 18(-0.25,-3.4) 19(0.25,-3.4) 20(0.75,-3.4) 21(1.25,-3.4) 22(1.75,-3.4) 23(2.25,-3.4) 24(2.75,-3.4) 37(2.75,3.4) 38(2.25,3.4) 39(1.75,3.4) 40(1.25,3.4) 41(0.75,3.4) 42(0.25,3.4) 43(-0.25,3.4) 44(-0.75,3.4) 45(-1.25,3.4) 46(-1.75,3.4) 47(-2.25,3.4) 48(-2.75,3.4)
  rect 4.1x4.1 smd paste-2.575: 49(0,0)
  silkscreen extent -3.72,-3.72 3.72,3.72, body extent -3.57,-3.58 3.58,3.57, height 1.01
Samtec_TFM-110-02-L-D-A [mm] "Samtec"
  rect 0.74x2.92 smd paste+0: 1(-5.715,-1.715) 2(-5.715,1.715) 3(-4.445,-1.715) 4(-4.445,1.715) 5(-3.175,-1.715) 6(-3.175,1.715) 7(-1.905,-1.715) 8(-1.905,1.715) 9(-0.635,-1.715) 10(-0.635,1.715) 11(0.635,-1.715) 12(0.635,1.715) 13(1.905,-1.715) 14(1.905,1.715) 15(3.175,-1.715) 16(3.175,1.715) 17(4.445,-1.715) 18(4.445,1.715) 19(5.715,-1.715) 20(5.715,1.715)
  round 0.508 hole 1.45 unplated paste+0: MH1(-7.305,0) MH2(7.305,0)
  silkscreen extent -7.93,-3.49 7.95,2.87, body extent -7.93,-2.95 7.94,3.02, height 5.74
SMB [mil] "Molded Diode, 2-Leads, Body 5.4x3.6mm, IPC Medium Density, based on OnSemi component dimensions"
  rect 85x107.99 smd: 1(-87.01,0) 2(87.01,0)
  silkscreen extent -155,-82 125,82, body extent -106,-71 106,71, height 91
SML-P1_GREEN [mm] "ROHM"
  rect 0.5x0.6 smd: 1(-0.45,0) 2(0.45,0)
  silkscreen extent -0.95,-0.3 -0.95,0.3, body extent -0.53,-0.33 0.53,0.33, height 0.25
sod-323 [mm] "NXP recommended land pattern"
  rect 0.6x0.6 smd paste-0.05: 1(-1.1,0) 2(1.1,0)
  silkscreen extent -2.06,-0.86 1.53,0.86, body extent -1.3,-0.67 1.3,0.68, height 1.1
SOD-523 [mm] "NXP Semiconductor recommended land pattern, nominal STEP model"
  rect 0.8x0.6 smd paste-0.05: 1(-0.55,0) 2(0.55,0)
  silkscreen extent -1.6,-0.63 1.2,0.64, body extent -0.8,-0.4 0.8,0.4, height 0.72
SOT-23 [mm] "SOT23, 3-Leads, Body 2.9x1.3mm, Pitch 0.95mm, Lead Span 2.5mm, IPC Medium Density"
  rect 1.5x0.6 smd: 1(-0.95,0.95) 2(-0.95,-0.95) 3(0.95,0)
  silkscreen extent 0.2,-1.5 0.7,1.5, body extent -1.16,-1.45 1.21,1.45, height 1
SW_FSM4JSMA [mm] "Alcoswitch"
  rect 1.4x2.1 smd: 1(2.25,4.55) 2(2.25,-4.55) 3(-2.25,4.55) 4(-2.25,-4.55)
  silkscreen extent -3,-3 3,5.4, body extent -3,-5 3,5, height 5.1
TI_Stacked_Overlay_Medium [mil]
  silkscreen extent -576,-136 576,134
TSW-104-07-G-D [mm] "Samtec 100mil, 2x4, 230 mil above insulator"
  rect 1.65x1.65 hole 1.016 mask+0: 1(-3.81,-1.27)
  round 1.65 hole 1.016 mask+0: 2(-3.81,1.27) 3(-1.27,-1.27) 4(-1.27,1.27) 5(1.27,-1.27) 6(1.27,1.27) 7(3.81,-1.27) 8(3.81,1.27)
  silkscreen extent -6.1,-2.54 5.08,2.54, body extent -5.08,-2.54 5.08,2.54, height 8.38
XTAL_CSM-7X [mm] "ECS"
  rect 5.5x2 smd: 1(-4.75,0) 2(4.75,0)
  silkscreen extent -6.2,-2.5 6.2,2.5, body extent -5.95,-2.4 5.95,2.4, height 4.3
YFQ0012AKAR [mm] "WCSP, 12-Leads, Body 1.94x1.43mm, Pitch 0.4mm"
  round 0.23 smd paste-0.13 mask+0.025: A1(-0.4,0.6) A2(0,0.6) A3(0.4,0.6) B1(-0.4,0.2) B2(0,0.2) B3(0.4,0.2) C1(-0.4,-0.2) C2(0,-0.2) C3(0.4,-0.2) D1(-0.4,-0.6) D2(0,-0.6) D3(0.4,-0.6)
  silkscreen extent -0.85,1.03 -0.75,1.12, body extent -0.71,-0.97 0.71,0.97, height 0.68

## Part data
C1 C34: "CAP, CERM, 2.2uF, 10V, +/-10%, X7R, 0603"
C2 C3: library part Capacitor, "CAP, CERM, xxxF, xxV, [TempCo], xx%, [PackageReference]"
C4: "CAP, CERM, 2.2 µF, 10 V, +/- 10%, X7R, 0603"
C5 C6: "CAP, CERM, 10 µF, 6.3 V, +/- 20%, X7R, 0805"
C7: "CAP, CERM, 1000pF, 2000V, +/-10%, X7R, 1210"
C9 C16 C18 C19 C20 C21 C22 C23 C26 C28 C31 C32 C33: "CAP, CERM, 1uF, 16V, +/-10%, X7R, 0603"
C10 C15 C17: "CAP, CERM, 2200pF, 50V, +/-10%, X7R, 0402"
C11 C14 C27: "CAP, CERM, 0.1uF, 16V, +/-10%, X7R, 0402"
C24 C25: "CAP, CERM, 18pF, 100V, +/-5%, C0G/NP0, 0603"
C29 C30: "CAP, CERM, 82 pF, 50 V, +/- 5%, C0G/NP0, 0402"
C35: "CAP, CERM, 1uF, 50V, +/-10%, X7R, 0603"
C36: "CAP, CERM, 0.01uF, 10V, +/-10%, X7R, 0201"
D1: "Diode, Zener, 5.6V, 550 mW, SMB"
D2 D3: "LED, Green, SMD"
D4: "Diode, Schottky, 40V, 0.25A, SOD-523"
D5: "Diode, Schottky, 5V, 0.03A, SOD-323"
D6: "Diode, TVS, Bi, 6 V, 600 W, SMB"
FID1 FID2 FID3 FID4 FID5 FID6: "Fiducial mark.  There is nothing to buy or mount."
H1 H2 H5 H7 H8 H11 H13: "Standoff, Hex, 0.5\"L #4-40 Nylon"
H3 H4 H6 H9 H10 H12 H14: "Machine Screw, Round, #4-40 x 1/4, Nylon, Philips panhead"
J1: "Connector, Receptacle, Mini-USB Type B, R/A, Top Mount SMT"
J2: "Header, 100mil, 2x1, Tin plated, TH"
J3: "Header, 100mil, 2x1, Tin, TH"
J4: "Header (shrouded), 100 mil, 7x2, Gold plated, TH"
J5: "Header, 100mil, 4x2, Gold, TH"
J6 J7: "Straight Low Profile Header, 10x2 Position,1.27 mm Pitch, SMT"
J9: "Header, 3x1, 100mil, SMT"
L1 L3 L5: "1.5A Ferrite Bead, 330 ohm @ 100MHz, SMD"
L4: "Inductor, Shielded, Ferrite, 10uH, 0.47A, 0.24 ohm, SMD"
LBL1: library part THT-14-423-10, "Thermal Transfer Printable Labels, 0.650\" W x 0.200\" H - 10,000 per roll"
Logo1: library part TI_Logo, "Texas Instrument Corporate Signature"
Q1 Q2: "MOSFET, N-CH, 50V, 0.22A, SOT-23"
R1 R8 R13 R14 R15 R16 R17 R18 R19 R20 R21 R22 R23 R24 R25 R27 R28 R29: "RES, 0 ohm, 5%, 0.063W, 0402"
R2 R3: "RES, 4.99k ohm, 1%, 0.063W, 0402"
R4 R5 R6: "RES, 47.5k ohm, 1%, 0.1W, 0603"
R7 R30: "RES, 0, 5%, 0.063 W, 0402"
R9 R10: "RES, 221 ohm, 1%, 0.063W, 0402"
R11 R12: "RES, 38.3 k, 1%, 0.063 W, 0402"
R26: "RES, 10.0k ohm, 1%, 0.063W, 0402"
R31 R34 R35 R38 R39 R42 R43 R46: "RES, 0 ohm, 5%, 1W, 2512"
S1 S2 S3: "Switch, Tactile, SPST-NO, 0.05A, 12V, SMT"
SH-J1 SH-J2 SH-J4 SH-J5: "Shunt, 2mm, Gold plated, Black"
TP1 TP3: "Test Point, Miniature, Red, TH"
TP2 TP13 TP14 TP15 TP16: "Test Point, Miniature, Black, TH"
TP4 TP5 TP11 TP12: "Test Point, Miniature, Yellow, TH"
TP6 TP7 TP8 TP9 TP10: "Test Point, Miniature, Orange, TH"
U1: "ULTRA LOW-NOISE, 250-mA LINEAR REGULATOR FOR RF AND ANALOG CIRCUITS REQUIRES NO BYPASS CAPACITOR, DBV0005A"
U3: "Mixed Signal Microcontroller, RGZ0048B"
U4: "Module, 128x64-pixel graphics display"
U5 U6 U8 U9 U10 U11: "ESD in 0402 Package with 10 pF Capacitance and 6 V Breakdown, 1 Channel, -40 to +125 degC, 2-pin X2SON (DPY), Green (RoHS & no Sb/Br)"
U7: "4-Channel Capacitance-to-Digital Converter for Capacitive Sensing Solutions, DSC0010B"
U12: "LM3630A High-Efficiency Dual-String White LED Driver, YFQ0012AKAR"
U13: "High-Accuracy, Low-Power, Digital Temperature Sensor With SMBus(TM)/Two-Wire Serial Interface, DRL0006A"
Y1: "Crystal, 8MHz, 18pF, SMD"
ZZ1: library part AssemblyNoteLabel
ZZ2 ZZ3 ZZ4 ZZ5 ZZ6 ZZ6.A ZZ6.B ZZ6.C ZZ6.D: library part AssemblyNote

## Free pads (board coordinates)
  round 314.96 hole 125.98: ""(5515,1000) ""(5515,2500)

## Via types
v1: diameter 20, hole 10, Layer 1 - Top Layer to Layer 4 - Bottom Layer, 320 vias
v2: diameter 19.68, hole 7.87, Layer 1 - Top Layer to Layer 4 - Bottom Layer, 12 vias

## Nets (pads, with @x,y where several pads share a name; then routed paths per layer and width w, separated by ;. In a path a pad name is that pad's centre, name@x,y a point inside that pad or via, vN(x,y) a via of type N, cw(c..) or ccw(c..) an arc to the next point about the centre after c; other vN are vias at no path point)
3V3: C5.1 C9.2 C11.2 C18.1 C34.1 D2.2 D3.2 D5.2 J3.2 J9.2 L3.1 L4.1 L5.1 R2.2 R3.2 R4.2 R5.2 R6.2 TP3.1 U3.37 U4.34 U4.35 U12.C3 | length 737.5
  Layer 1 - Top Layer w8: U12.C3@8551.28,3431.44 8551.89,3432.05 8557.8,3432.05 8584.92,3404.92
  Layer 1 - Top Layer w10: L4.1@8704.92,3423.35 L4.1@8714.93,3433.35
  Layer 1 - Top Layer w15: v1@7740.71,900.25 D2.2@7740.71,937.4 ; v1@8095.71,900.71 D3.2@8095.71,937.86
  Layer 1 - Top Layer w20: v1(8298,7153) D5.2@8337.69,7153
  Layer 1 - Top Layer w25: 8584.92,3404.92 8608.42,3381.42 C34.1@8704.92,3381.42 ; L4.1@8704.92,3423.35 C34.1@8704.92,3381.42 ; v1(8748.42,3381.42) C34.1@8704.92,3381.42
  Layer 1 - Top Layer w30: v1(7497.38,5028.76) R4.2@7545,5028.76 ; v1(7595,5235) L5.1@7595,5283.5 ; v1(7743.62,5310) R3.2@7743.62,5340 ; v1(7856.38,5310) R2.2@7856.38,5340 ; v1@8260.25,600 R5.2@8260.25,647.62 ; v1@8900.25,600 R6.2@8900.25,647.62
  Layer 4 - Bottom Layer w30: U4.34@7150,1790 7221.5,1790 C18.1@7240,1808.5
  other v1: 8260,600 8900,600 7740.46,900.25 8095.46,900.71 7758,4500 7758,4540 7758,4580
A0_SCLK: R20.2 TP8.1 U3.11 U4.37 | length 6766.8
  Layer 1 - Top Layer w8: R20.2@7623.62,6970 v1(7670,6970) ; U3.11@7963.86,4908.58 8081.42,4908.58 v1(8110,4880)
  Layer 4 - Bottom Layer w8: U4.37@7150,1490 7660,2000 TP8.1@7660,3600 8155.16,4095.16 8155.16,4679.84 8110,4725 v1(8110,4880) 8030,4960 7875,4960 7785,5050 7785,5105 8025,5345 8070,5345 8205,5480 8205,6435 v1(7670,6970)
A0_SIMO: R19.2 TP6.1 U3.24 U4.36 | length 6065.3
  Layer 1 - Top Layer w8: TP6.1@7250.18,3599.88 7250.18,4463.46 7525,4738.28 7525,4930 7555,4960 v1(7600,4960) 7675,4960 7681.14,4953.86 U3.24@7721.73,4953.86 ; v1(7455,6370) 7665,6580 7665,6870 7625,6910 R19.2@7623.62,6910
  Layer 4 - Bottom Layer w8: U4.36@7150,1590 7460,1900 7460,3390.06 TP6.1@7250.18,3599.88 ; TP6.1@7250,3599.88 TP6.1@7250,3600 ; v1(7455,6370) 7435,6350 7435,5035 7510,4960 v1(7600,4960)
A0_SOMI: R17.1 TP7.1 U3.25 | length 3643
  Layer 1 - Top Layer w8: v1(7455,6415) 7623.62,6583.62 R17.1@7623.62,6850 ; TP7.1@7460,3600 7415,3645 7415,4603.28 7545,4733.28 7545,4905 v1(7568.27,4928.27) U3.25@7696.14,4928.27
  Layer 4 - Bottom Layer w8: v1(7455,6415) 7415,6375 7415,5025 7511.73,4928.27 v1(7568.27,4928.27)
A1_RX: R13.1 R27.1 TP4.1 U3.21 | length 8287.8
  Layer 1 - Top Layer w8: R13.1@7196.38,7128.21 7190,7121.83 7190,6415 TP4.1@7720,5885 7955,5650 7955,5274.21 7900,5219.21 7900,5135 7780.79,5015.79 U3.21@7780.79,4953.86
  Layer 4 - Bottom Layer w8: v1(7875,5110) 8295,5110 8625,4780 8625,4425 8495,4295 8495,3726.28 8050,3281.28 8050,480 8105,425 8245,425 8300,370 R27.1@8300,368.62
A1_TX: R14.1 R28.1 TP5.1 U3.20 | length 8315.2
  Layer 1 - Top Layer w8: v1(7140,7190) 7194.59,7190 R14.1@7196.38,7188.21 ; v1(7250,6515) TP5.1@7880,5885 7975,5790 7975,5255 7920,5200 7920,5115 v1(7875,5070) 7800.47,4995.47 U3.20@7800.47,4953.86
  Layer 4 - Bottom Layer w8: v1(7140,7190) 7140,6625 v1(7250,6515) ; v1(7875,5070) 8300,5070 8605,4765 8605,4435 8475,4305 8475,3736.28 8030,3291.28 8030,470 8095,405 8167.56,405 8200,372.56 R28.1@8200,368.62
AVCC: C6.1 C14.2 C16.2 L3.2 U3.48
  other v1: 7902,4500 7902,4540 7902,4580
AVCC_FLT: C23.1 C27.2 C36.1 L5.2 R26.2 U7.8 U13.5 | length 827.4
  Layer 1 - Top Layer w10: R26.2@7368.62,5580 7360,5588.62 7360,5635 7370,5645 U13.5@7389.53,5645 C36.1@7437.01,5645 ; U7.8@7409,5360.73 U7.8@7416.25,5360.73 7438.27,5360.73 7450.38,5348.62 C27.2@7480,5348.62
  Layer 1 - Top Layer w15: C36.1@7437.01,5645 7437.01,5672.01 7450,5685 7480,5685
  Layer 1 - Top Layer w30: 7480,5685 7545,5685 7595,5635 L5.2@7595,5346.5 C23.1@7535,5346.5 7532.5,5349 C27.2@7484,5349
B0_SCL: R2.1 TP12.1 U3.32 U7.9 U12.A2 U13.1 | length 4553.6
  Layer 1 - Top Layer w8: U13.1@7330.47,5664.69 7330.47,5710.47 7375,5755 7695,5755 7880,5570 TP12.1@7880,5440 7880,5390 7903.62,5366.38 R2.1@7903.62,5345 ; U7.9@7416.25,5380.42 7470.42,5380.42 v1(7520,5430) ; v1(7655,4780) 7665.47,4790.47 U3.32@7696.14,4790.47 ; v1(7795,3820) 7795,3515 7825,3485 8525,3485 8534.92,3475.08 U12.A2@8534.92,3463.54
  Layer 4 - Bottom Layer w8: v1(7520,5430) 7520,5490 7550,5520 7800,5520 TP12.1@7880,5440 7880,5385 7705,5210 7705,4795 7690,4780 v1(7655,4780) 7500,4625 7500,4115 v1(7795,3820)
B0_SDA: R3.1 TP11.1 U3.31 U7.10 U12.A1 U13.6 | length 4060.4
  Layer 1 - Top Layer w8: U13.6@7389.53,5664.69 7389.53,5689.53 7420,5720 7605,5720 7720,5605 TP11.1@7720,5440 7720,5390 7696.38,5366.38 R3.1@7696.38,5345 ; U7.10@7416.25,5400.1 7435.1,5400.1 7510,5475 v1(7550,5475) ; v1(7615,4780) 7645.16,4810.16 U3.31@7696.14,4810.16 ; v1(7770,3775) 7770,3510 7816.46,3463.54 U12.A1@8519.17,3463.54
  Layer 4 - Bottom Layer w8: v1(7550,5475) 7685,5475 TP11.1@7720,5440 7720,5375 7685,5340 7685,4825.85 7669.15,4810 7645,4810 v1(7615,4780) 7480,4645 7480,4065 v1(7770,3775)
BL_EN: U3.7 U12.B1 | length 2544.7
  Layer 1 - Top Layer w8: U3.7@7963.86,4829.84 8160.16,4829.84 8225,4765 8225,4295 7745,3815 7745,3505 7802.2,3447.8 U12.B1@8519.17,3447.8
BL_PWM: U3.26 U12.C1 | length 2492.7
  Layer 1 - Top Layer w8: v1(7595,4895) 7608.58,4908.58 U3.26@7696.14,4908.58 ; v1(7705,3775) 7725,3755 7725,3495 7787.95,3432.05 U12.C1@8519.17,3432.05
  Layer 4 - Bottom Layer w8: v1(7595,4895) 7460,4760 7460,4020 v1(7705,3775)
BLSW: D4.2 L4.2 U12.A3 | length 406.1
  Layer 1 - Top Layer w10: U12.A3@8550.67,3463.54 8589.92,3502.8 8589.92,3568.27 D4.2@8588.27,3569.92 8588.27,3603.27 8604.92,3619.92 8684.92,3619.92 8714.93,3589.92 L4.2@8714.93,3486.5
CIN1: J5.6 J5.8 R11.1 | length 427.9
  Layer 1 - Top Layer w10: J5.6@6890,5530 J5.8@6890,5430 6942.01,5377.99 R11.1@7196.38,5377.99
CIN2: R12.1 | length 4319.6
  Layer 1 - Top Layer w10: v1(7155,5295) 7193.39,5295 R12.1@7196.38,5297.99
  Layer 4 - Bottom Layer w10: 3360,5900 6945,5900 7100,5745 7100,5350 v1(7155,5295)
EM_CTS: J6.18 R15.1 | length 96.5
  Layer 1 - Top Layer w10: R15.1@7243.62,7280 7245.11,7278.51 J6.18@7339.47,7278.51
EM_RTS: J7.3 R24.2 | length 102
  Layer 1 - Top Layer w10: J7.3@8674.51,6928.51 8776.08,6928.51 R24.2@8776.38,6928.21
EM_RX: J6.14 R14.2 | length 99.9
  Layer 1 - Top Layer w10: R14.2@7243.62,7188.21 7246.83,7185 7332.98,7185 J6.14@7339.47,7178.51
EM_TX: J6.12 R13.2 | length 96
  Layer 1 - Top Layer w10: R13.2@7243.62,7128.21 7243.92,7128.51 J6.12@7339.47,7128.51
